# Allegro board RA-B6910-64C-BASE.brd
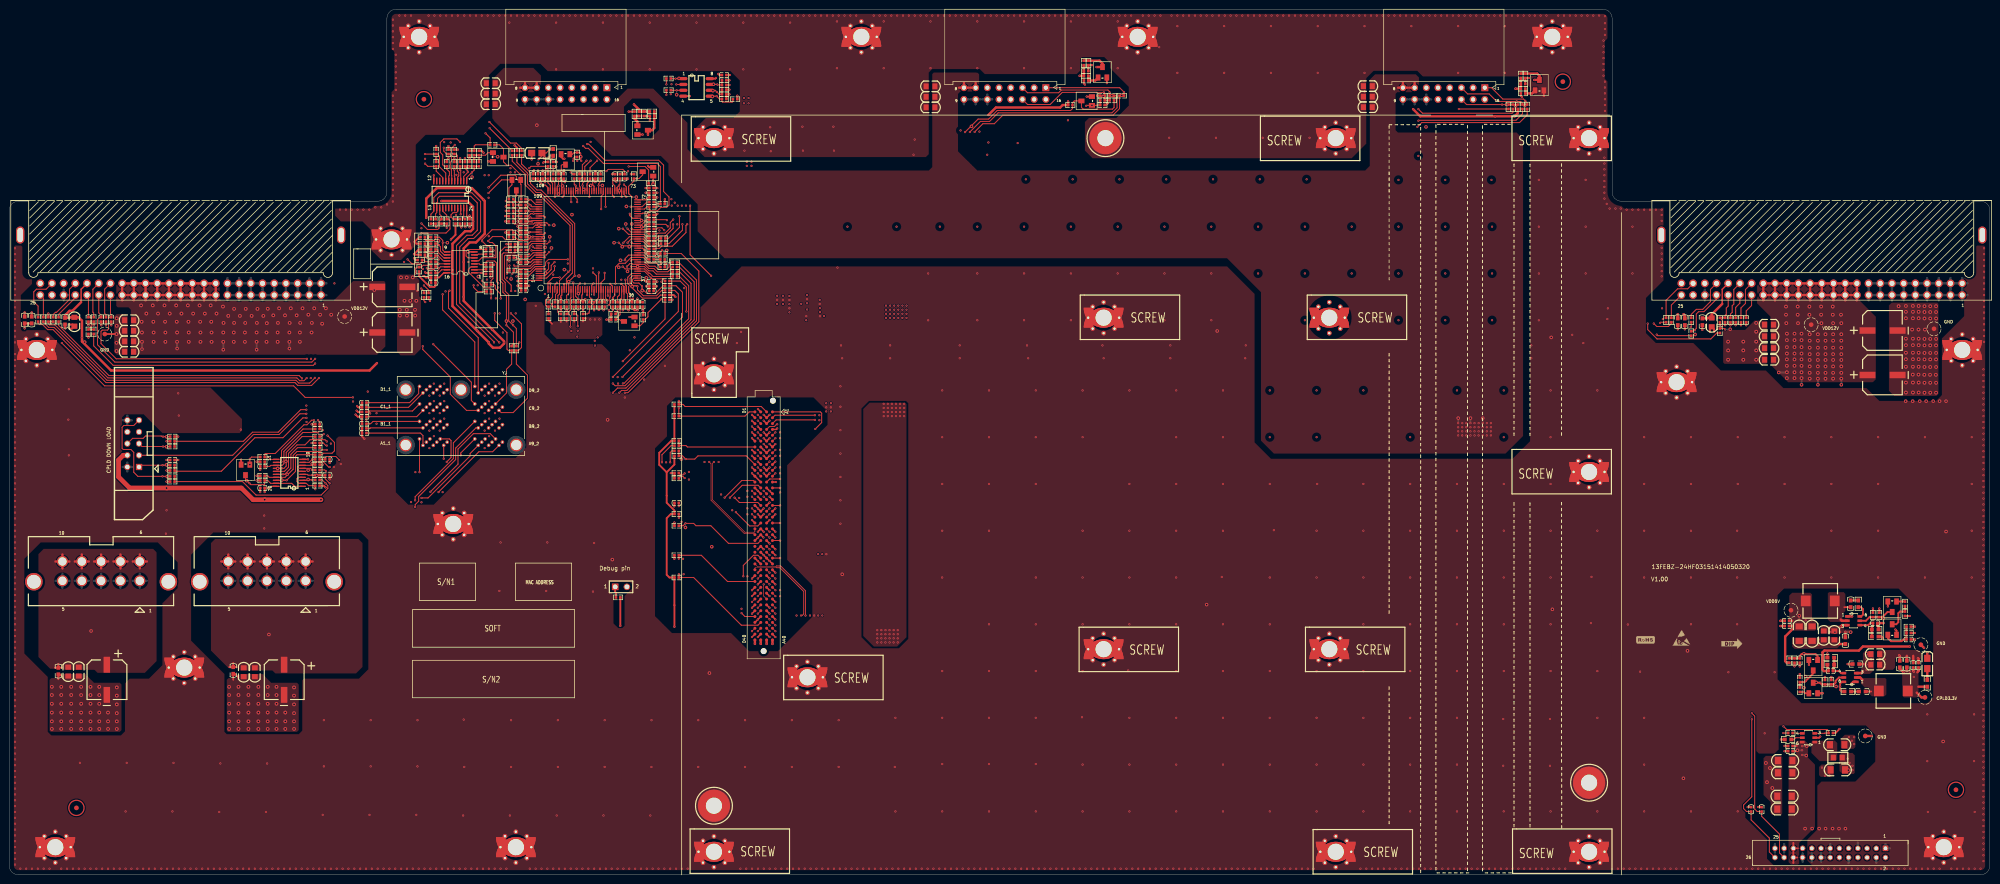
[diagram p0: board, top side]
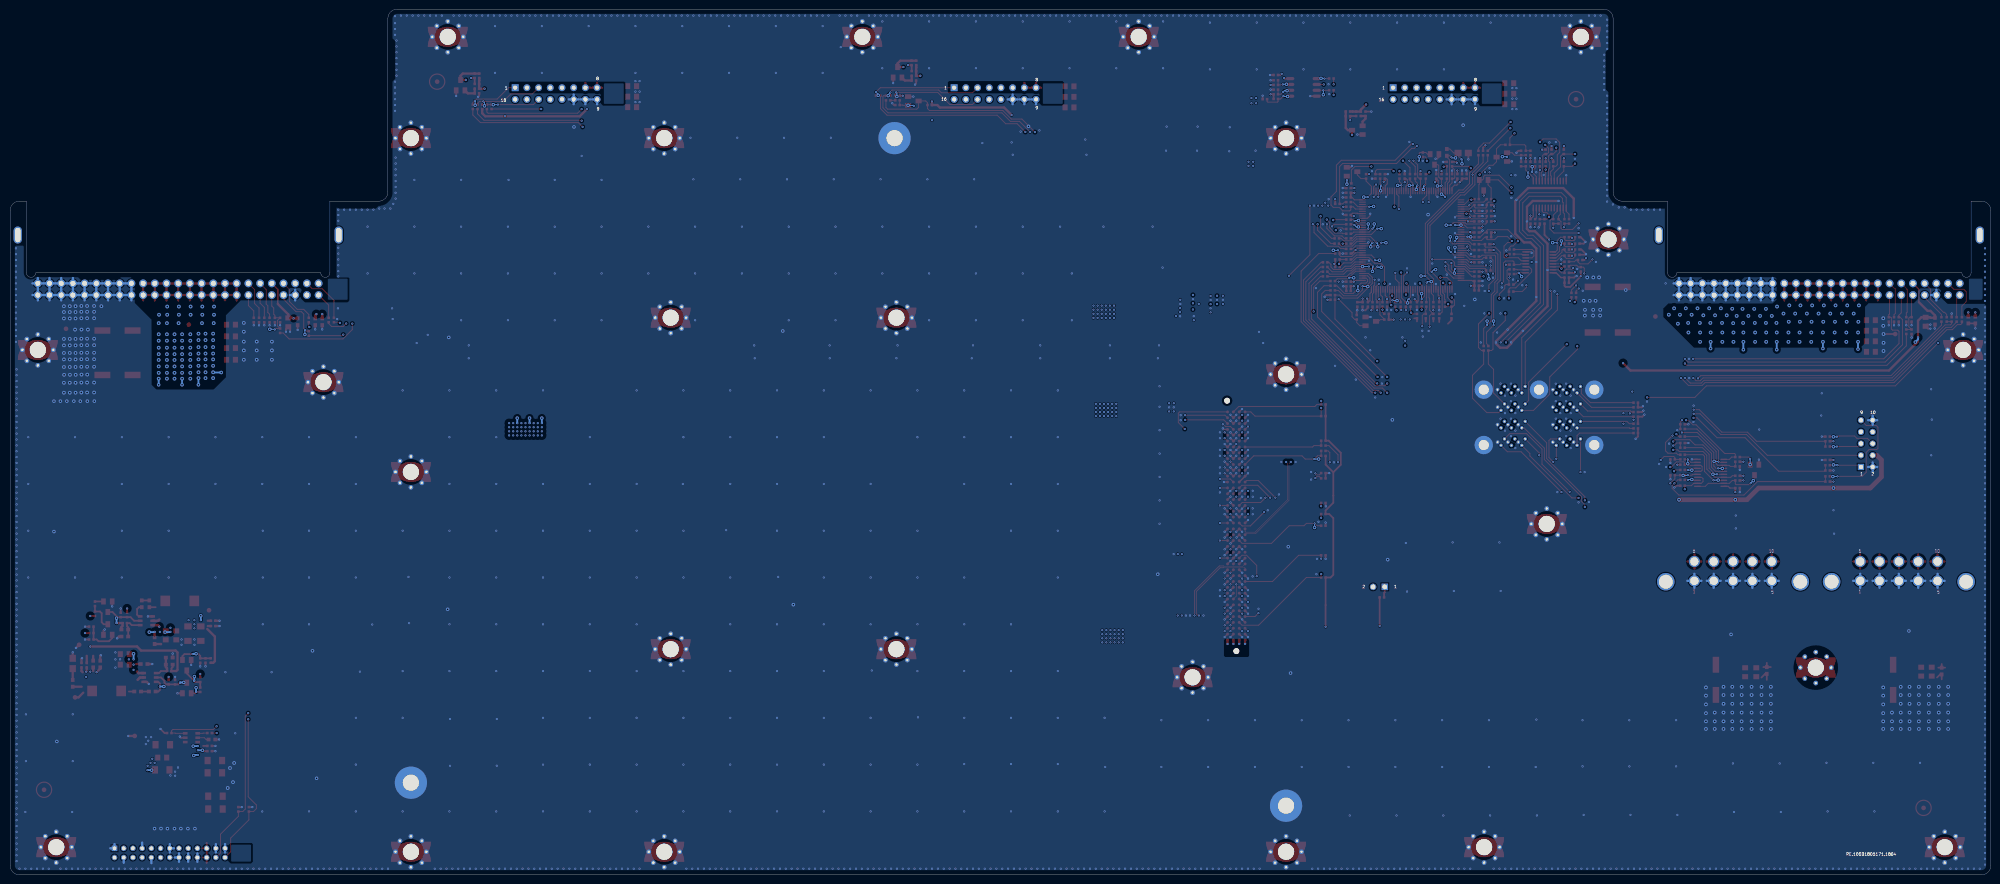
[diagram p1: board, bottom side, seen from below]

Outline 430 x 188 mm; copper layers: TOP, GND1, SIG1, GND2, SIG2, BOTTOM. Coordinates in mm from the lower left corner of the outline.
Outline path: 0,144.3 arc(0.12,144.98) 0.47,145.58 arc(1.15,146.11) 2,146.3 4.28,146.3 4.28,130.76 arc(4.39,130.31) 4.7,129.95 arc(5.46,129.78) 6.11,130.2 arc(6.24,130.47) 6.28,130.76 68.16,130.76 arc(68.21,130.46) 68.35,130.18 arc(69,129.78) 69.74,129.95 arc(70.05,130.31) 70.16,130.76 70.16,146.3 80,146.3 arc(81.41,146.89) 82,148.3 82,186 arc(82.59,187.41) 84,188 346,188 arc(347.41,187.41) 348,186 348,148.3 arc(348.59,146.89) 350,146.3 360.58,146.3 360.58,130.76 arc(360.69,130.31) 361,129.95 arc(361.76,129.78) 362.41,130.2 arc(362.54,130.47) 362.58,130.76 424.46,130.76 arc(424.51,130.46) 424.65,130.18 arc(425.3,129.78) 426.04,129.95 arc(426.35,130.31) 426.46,130.76 426.46,146.3 428,146.3 arc(429.41,145.71) 430,144.3 430,2 arc(429.41,0.59) 428,0 2,0 arc(0.59,0.59) 0,2 0,144.3

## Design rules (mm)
net group CIE_REFCLK_: nets PCIE_REFCLK_N PCIE_REFCLK_P
net group CU_CIE_RX0: nets CPU_PCIE_RXN0 CPU_PCIE_RXP0
net group CU_CIE_RX1: nets CPU_PCIE_RXN1 CPU_PCIE_RXP1
net group CU_CIE_RX2: nets CPU_PCIE_RXN2 CPU_PCIE_RXP2
net group CU_CIE_RX3: nets CPU_PCIE_RXN3 CPU_PCIE_RXP3
net group CU_CIE_TX0: nets CPU_PCIE_TXN0 CPU_PCIE_TXP0
net group CU_CIE_TX1: nets CPU_PCIE_TXN1 CPU_PCIE_TXP1
net group CU_CIE_TX2: nets CPU_PCIE_TXN2 CPU_PCIE_TXP2
net group CU_CIE_TX3: nets CPU_PCIE_TXN3 CPU_PCIE_TXP3
net group CU_KR_RD0: nets CPU_KR_RDN0 CPU_KR_RDP0
net group CU_KR_RD1: nets CPU_KR_RDN1 CPU_KR_RDP1
net group CU_KR_TD0: nets CPU_KR_TDN0 CPU_KR_TDP0
net group CU_KR_TD1: nets CPU_KR_TDN1 CPU_KR_TDP1
net group DP1: nets USB_DM USB_DP
net group MDI_0: nets MDI_0N MDI_0P
net group MDI_1: nets MDI_1N MDI_1P
net group MDI_2: nets MDI_2N MDI_2P
net group MDI_3: nets MDI_3N MDI_3P
net group USB_RX_: nets USB_RX_N USB_RX_P
net group USB_TX_: nets USB_TX_N USB_TX_P

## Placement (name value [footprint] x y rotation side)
C1  103  [C0402]  114.8 151.69 270 top
C2  0.1uF/25V  [C0402]  131.56 151.69 270 top
C3  0.1uF/25V  [C0402]  139.44 147.12 180 top
C4  0.1uF/25V  [C0402]  139.44 143.31 180 top
C5  103  [C0402]  136.39 123.88 90 top
C6  0.1uF/25V  [C0402]  111.62 128.96 0 top
C7  103  [C0402]  139.44 148.14 180 top
C8  0.1uF/25V  [C0402]  127.24 151.69 270 top
C9  0.1uF/25V  [C0402]  120.39 151.69 270 top
C10  0.1uF/25V  [C0402]  35.42 90.1 180 top
C16  1uF/25V  [C0402]  139.44 128.83 0 top
C17  1uF/25V  [C0402]  135.24 123.88 270 top
C18  10uF/6.3V  [C0402]  139.44 149.15 0 top
C19  10uF/6.3V  [C0402]  111.62 126.93 0 top
C20  10uF/6.3V  [C0402]  137.53 123.88 90 top
C21  0.1uF/25V  [C0402]  111.62 133.02 0 top
C22  103  [C0402]  111.62 127.94 0 top
C23  0.1uF/25V  [C0402]  139.44 134.93 180 top
C28  10uF/25V  [C0805]  200.01 166.68 0 top
C29  10uF/25V  [C0805]  200.01 168.96 180 top
C30  1uF/25V  [C0805]  200.01 171.25 180 top
C48  0.1uF/25V  [C0402]  124.58 123.88 90 top
C49  103  [C0402]  139.44 127.82 180 top
C50  103  [C0402]  131.05 123.88 90 top
C51  0.1uF/25V  [C0402]  119.75 123.88 90 top
C52  10uF/25V  [C0805]  104.55 171.93 0 top
C53  10uF/25V  [C0805]  104.55 169.64 180 top
C54  1uF/25V  [C0805]  104.55 167.36 180 top
C55  10uF/25V  [C0805]  294.97 171.3 0 top
C56  10uF/25V  [C0805]  294.97 169.01 180 top
C57  1uF/25V  [C0805]  294.97 166.72 180 top
C61  100P  [C0402]  111.62 144.2 180 top
C62  100P  [C0402]  111.62 145.47 180 top
C63  0.1uF/25V  [C0402]  54.98 84 0 top
C64  1uF/25V  [C0402]  111.62 139.5 180 top
C65  1uF/25V  [C0402]  111.62 141.91 180 top
C66  10uF/6.3V  [C0402]  113.78 151.69 90 top
C67  104  [C0603]  362.25 120.11 90 top
C68  104  [C0603]  363.78 120.11 90 top
C69  1uF/25V  [C0805]  382.07 111.86 0 top
C70  1uF/25V  [C0805]  382.07 114.4 0 top
C71  10uF/25V  [C0805]  382.07 116.94 0 top
C72  10uF/25V  [C0805]  382.07 119.48 0 top
C73  100P  [C0402]  374.83 120.5 90 top
C74  104  [C0603]  367.59 120.11 90 top
C75  100P  [C0402]  377.11 120.5 90 top
C77  10uF/25V  [C0805]  369.62 119.99 90 top
C78  100P  [C0402]  372.54 120.5 90 top
C79  104  [C0603]  3.35 120.5 90 top
C80  1uF/25V  [C0805]  26.02 115.88 0 top
C81  104  [C0603]  4.88 120.5 90 top
C82  1uF/25V  [C0805]  26.02 113.59 0 top
C83  10uF/25V  [C0805]  26.02 120.45 0 top
C84  10uF/25V  [C0805]  26.02 118.16 0 top
C85  100P  [C0402]  19.99 120.62 90 top
C86  100P  [C0402]  22.15 120.62 90 top
C87  104  [C0603]  12.12 120.24 90 top
C89  10uF/25V  [C0805]  14.15 120.11 90 top
C90  100P  [C0402]  17.2 120.62 90 top
C91  104  [C0603]  402.33 39.8 0 top
C92  X  [C0402]  395.47 44.25 0 top
C94  104  [C0603]  400.93 45.77 180 top
C95  10uF/25V  [C0805]  405.12 47.93 0 top
C96  10uF/25V  [C0805]  405.12 45.65 0 top
C97  22uF/6.3V  [C0603]  410.45 45.77 90 top
C98  22uF/6.3V  [C0603]  411.98 45.77 90 top
C99  1uF/25V  [C0402]  414.52 45.52 90 top
C100  0.1uF/25V  [C0402]  413.37 45.52 270 top
C101  X  [C0402]  412.38 51.11 180 top
C102  104  [C0603]  399.79 58.85 270 top
C103  X  [C0402]  405.12 54.66 180 top
C104  33uF/10V  [C1206]  396.99 22.79 180 top
C105  33uF/10V  [C1206]  396.86 28.25 0 top
C106  33uF/10V  [C1206]  385.56 24.82 180 top
C107  33uF/10V  [C1206]  385.56 22.15 180 top
C108  104  [C0603]  398.64 50.85 270 top
C109  10uF/25V  [C0805]  396.23 52 270 top
C110  10uF/25V  [C0805]  393.94 52 270 top
C111  33uF/10V  [C1206]  391.4 52.38 270 top
C112  33uF/10V  [C1206]  388.61 52.38 270 top
C113  1uF/25V  [C0402]  385.94 55.17 180 top
C114  0.1uF/25V  [C0402]  385.94 54.03 0 top
C116  0.1uF/25V  [C0402]  155.22 173.71 0 top
C117  0.1uF/25V  [C0402]  99.94 141.91 90 top
C120  33uF/10V  [C1206]  385.43 14.28 180 top
C121  33uF/10V  [C1206]  385.43 17.07 180 top
C129  X  [C0402]  380.46 14.22 90 top
C130  X  [C0402]  378.18 14.22 90 top
C131  104  [C0603]  10.66 44.25 90 top
C132  1uF/25V  [C0805]  12.82 44.12 90 top
C133  10uF/25V  [C0805]  15.1 44.12 90 top
C134  X  [C0402]  54.98 88.7 180 top
C135  X  [C0402]  69.08 86.79 0 top
C136  X  [C0402]  66.92 93.78 180 top
C137  X  [C0402]  66.92 97.84 180 top
C138  X  [C0402]  69.08 90.22 0 top
C139  X  [C0402]  133.59 151.69 270 top
C140  X  [C0402]  118.1 154.36 90 top
C141  X  [C0402]  142.86 125.91 0 top
C142  X  [C0402]  77.08 95.94 180 top
C143  X  [C0402]  77.08 96.95 180 top
C144  X  [C0402]  77.08 99.49 180 top
C145  X  [C0402]  77.08 97.97 180 top
C146  X  [C0402]  77.08 100.51 180 top
C147  X  [C0402]  77.08 102.54 180 top
C148  X  [C0402]  77.08 101.53 180 top
C149  X  [C0402]  144.9 80.77 180 top
C150  X  [C0402]  388.74 46.54 90 top
C151  104  [C0603]  48.63 44.38 90 top
C152  1uF/25V  [C0805]  53.33 44 90 top
C153  10uF/25V  [C0805]  50.92 44 90 top
C154  0.1uF/25V  [C0402]  92.06 129.72 0 top
C155  1uF/25V  [C0402]  92.06 128.58 0 top
C156  1uF/25V  [C0402]  115.81 151.69 270 top
C157  10uF/6.3V  [C0402]  139.44 126.8 180 top
C158  0.1uF/25V  [C0402]  386.7 26.85 0 top
CD1  220uF/25V  [CDNCC_0810]  406.7 118.21 180 top
CD2  220uF/25V  [CDNCC_0810]  406.7 108.56 180 top
CD4  220uF/25V  [CDNCC_0810]  83.17 117.78 180 top
CD5  220uF/25V  [CDNCC_0810]  83.17 127.69 180 top
CD7  220uF/25V  [CDNCC_0810]  21.2 42.34 90 top
CD8  220uF/25V  [CDNCC_0810]  59.68 42.34 90 top
D1  17_21_G6C_FM1N2B_3T  [LED_SMT0805]  114.54 156.77 0 top
D2  BAT54A  [SOT_23]  110.1 149.79 90 top
D3  17_21_G6C_FM1N2B_3T  [LED_SMT0805]  416.42 45.9 270 top
FD5  -  [MARK]  337.3 172.27 0 top
FD8  -  [MARK]  14.59 14.53 0 top
FD9  -  [MARK]  422.65 18.47 0 top
FD12  -  [MARK]  90.03 168.46 0 top
J1  -  [MOLEX_44068_0048]  64.35 63.85 0 top
J2  -  [C210R3-11631-Y]  320.36 170.95 180 top
J3  -  [MOLEX_44068_0048]  28.36 63.85 0 top
J4  -  [C210R3-11631-Y]  225.06 170.95 180 top
J5  -  [C210R3-11631-Y]  129.76 170.95 180 top
J7  -  [JP_10]  28.18 88.57 90 top
J8  -  [C210Q5_15033_Y]  424 125.91 180 top
J9  -  [C210Q5_15033_Y]  67.7 125.91 180 top
J10  -  [C200126087D6001P]  407.35 5.75 180 top
J11  -  [CON_2]  131.56 62.54 0 top
L1  3.3uH/3.8A  [L_7M50X7M50X4M70]  409.06 39.93 180 top
L2  3.3uH/3.8A  [L_7M50X7M50X4M70]  393.18 59.49 0 top
L3  300/2A  [L0805]  396.99 25.45 0 top
NOREF  -  []  95.08 93.97 90 top
NOREF#2  -  []  339.28 172.94 0 top
NOREF#3  -  []  87.45 113.52 90 top
NOREF#4  -  []  378.1 -31.45 90 top
NOREF#5  -  []  219.64 156.54 90 top
NOREF#6  -  []  105.4 48.44 0 top
NOREF#7  -  []  165.8 102.97 0 top
NOREF#8  -  []  167.37 54.07 0 top
NOREF#9  -  []  400.53 41.3 0 top
NOREF#10  -  []  402.38 114.91 0 top
NOREF#11  -  []  124.34 156.54 0 top
NOREF#12  -  []  124.34 172.94 0 top
NOREF#13  -  []  224.25 46.91 90 top
NOREF#14  -  []  55.42 38.07 0 top
NOREF#15  -  []  410.64 131.81 90 top
NOREF#16  -  []  67.7 128.45 90 top
NOREF#17  -  []  126.12 172.94 0 top
NOREF#18  -  []  425.02 143.48 180 top
NOREF#19  -  []  161.9 100.54 0 top
NOREF#20  -  []  389.77 28.22 0 top
NOREF#21  -  []  221.42 172.94 0 top
NOREF#22  -  []  161.9 51.01 90 top
NOREF#23  -  []  207.28 168.41 0 top
NOREF#24  -  []  4.88 143.56 0 top
NOREF#25  -  []  93.58 94.67 0 top
NOREF#26  -  []  314.94 156.54 90 top
NOREF#27  -  []  207.28 168.41 90 top
NOREF#28  -  []  363.04 125.91 0 top
NOREF#29  -  []  2.38 138.95 0 top
NOREF#30  -  []  81 174.68 180 top
NOREF#31  -  []  78.85 124.39 0 top
NOREF#32  -  []  412.81 40.63 0 top
NOREF#33  -  []  316.72 172.94 0 top
NOREF#34  -  []  166.97 105.11 0 top
NOREF#35  -  []  243.98 172.94 0 top
NOREF#36  -  []  207.28 170.95 0 top
NOREF#37  -  []  389.43 55.74 90 top
NOREF#38  -  []  16.93 38.07 0 top
NOREF#39  -  []  -69.52 146.43 0 top
NOREF#40  -  []  349 176.96 0 top
NOREF#41  -  []  282.9 146.43 0 top
NOREF#42  -  []  74.63 147.3 90 top
NOREF#43  -  []  399.07 56.12 0 top
NOREF#44  -  []  74.09 103.19 90 top
NOREF#45  -  []  310.2 168.41 0 top
NOREF#46  -  []  314.94 156.54 0 top
NOREF#47  -  []  358.68 138.95 0 top
NOREF#48  -  []  425 183 270 top
NOREF#49  -  []  14.98 131.81 90 top
NOREF#50  -  []  163.79 48.58 90 top
NOREF#51  -  []  84.25 108.24 0 top
NOREF#52  -  []  402.38 105.26 0 top
NOREF#53  -  []  403.43 118.21 0 top
NOREF#54  -  []  95.08 135.3 0 top
NOREF#55  -  []  111.98 168.41 0 top
NOREF#56  -  []  99.82 130.48 90 top
NOREF#57  -  []  2.38 138.95 0 top
NOREF#58  -  []  410.98 113.95 90 top
NOREF#59  -  []  78.85 114.48 0 top
NOREF#60  -  []  214.9 168.41 0 top
NOREF#61  -  []  65.16 125.91 0 top
NOREF#62  -  []  107.08 93.97 90 top
NOREF#63  -  []  430.39 103.19 90 top
NOREF#64  -  []  79.9 127.69 0 top
NOREF#65  -  []  165.8 102.97 0 top
NOREF#66  -  []  167.37 46.91 0 top
NOREF#67  -  []  16.93 38.07 0 top
NOREF#68  -  []  399.55 56.72 0 top
NOREF#69  -  []  55.42 38.07 0 top
NOREF#70  -  []  101.84 130.36 90 top
NOREF#71  -  []  389.43 63.24 0 top
NOREF#72  -  []  148.68 172.94 0 top
NOREF#73  -  []  424 125.91 90 top
NOREF#74  -  []  398.31 41.9 0 top
NOREF#75  -  []  340.06 156.54 90 top
NOREF#76  -  []  302.58 168.41 90 top
NOREF#77  -  []  354.7 147.3 90 top
NOREF#78  -  []  92.83 93.97 0 top
NOREF#79  -  []  358.68 138.95 0 top
NOREF#80  -  []  421.46 125.91 0 top
NOREF#81  -  []  167.37 46.91 90 top
NOREF#82  -  []  67.7 125.91 90 top
NOREF#83  -  []  21.2 39.07 90 top
NOREF#84  -  []  389.77 28.22 90 top
NOREF#85  -  []  424 128.45 90 top
NOREF#86  -  []  164.44 51.01 0 top
NOREF#87  -  []  161.9 57.36 90 top
NOREF#88  -  []  95.08 134.65 90 top
NOREF#89  -  []  383.35 3.75 0 top
NOREF#90  -  []  6.74 128.45 90 top
NOREF#91  -  []  244.76 156.54 90 top
NOREF#92  -  []  410.98 104.29 90 top
NOREF#93  -  []  124.34 156.54 90 top
NOREF#94  -  []  166.97 108.82 90 top
NOREF#95  -  []  363.08 50.35 0 top
NOREF#96  -  []  94.33 93.27 90 top
NOREF#97  -  []  111.98 168.41 90 top
NOREF#98  -  []  111.98 170.95 0 top
NOREF#99  -  []  89.08 106.07 90 top
NOREF#100  -  []  87.45 123.42 90 top
NOREF#101  -  []  402.28 41.3 90 top
NOREF#102  -  []  161.9 51.01 0 top
NOREF#103  -  []  6.74 125.91 0 top
NOREF#104  -  []  397.81 39.23 90 top
NOREF#105  -  []  167.37 46.91 90 top
NOREF#106  -  []  72.06 138.95 90 top
NOREF#107  -  []  -62.73 168.05 0 top
NOREF#108  -  []  79.9 117.78 0 top
NOREF#109  -  []  403.43 108.56 0 top
NOREF#110  -  []  58.16 131.81 90 top
NOREF#111  -  []  428.36 138.95 90 top
NOREF#112  -  []  302.58 168.41 0 top
NOREF#113  -  []  59.68 39.07 90 top
NOREF#114  -  []  163.79 48.58 90 top
NOREF#115  -  []  401.3 53.62 90 top
NOREF#116  -  []  119.6 168.41 0 top
NOREF#117  -  []  401.77 55.17 90 top
NOREF#118  -  []  168.32 105.11 90 top
NOREF#119  -  []  389.29 28.82 0 top
NOREF#120  -  []  405.91 39.93 0 top
NOREF#121  -  []  96.13 130.47 90 top
NOREF#122  -  []  84.25 91.04 90 top
NOREF#123  -  []  -3.54 146.43 0 top
NOREF#124  -  []  219.64 156.54 0 top
NOREF#125  -  []  373.37 50.98 0 top
NOREF#126  -  []  372.54 131.81 90 top
NOREF#127  -  []  219.64 172.94 0 top
NOREF#128  -  []  95.08 105.37 90 top
NOREF#129  -  []  354.95 50.98 0 top
NOREF#130  -  []  314.94 172.94 0 top
NOREF#131  -  []  398.31 41.9 90 top
NOREF#132  -  []  107.08 93.97 90 top
NOREF#133  -  []  107.08 93.97 90 top
NOREF#134  -  []  89.08 106.07 0 top
NOREF#135  -  []  390.03 59.49 0 top
NOREF#136  -  []  286.78 146.43 0 top
NOREF#137  -  []  149.46 156.54 90 top
NOREF#138  -  []  352.76 146.43 0 top
NOREF#139  -  []  -73.4 146.43 0 top
NOREF#140  -  []  363.04 128.45 90 top
NOREF#141  -  []  293.57 168.05 0 top
NOREF#142  -  []  224.25 46.91 90 top
NOREF#143  -  []  302.58 170.95 0 top
NOREF#144  -  []  5 183 270 bottom
Q1  MMBT3904LT1G  [SOT_23]  120.77 155.37 90 top
Q3  MMBT3904LT1G  [SOT_23]  138.67 152.71 0 top
Q4  MMBT3904LT1G  [SOT_23]  51.3 87.94 90 top
Q7  MMBT3904LT1G  [SOT_23]  408.8 58.22 90 top
Q8  MMBT3904LT1G  [SOT_23]  408.8 53.27 270 top
Q9  MMBT3904LT1G  [SOT_23]  391.66 40.57 270 top
Q10  MMBT3904LT1G  [SOT_23]  391.66 45.52 90 top
Q11  MMBT3904LT1G  [SOT_23]  134.61 120.2 0 top
Q12  MMBT3904LT1G  [SOT_23]  233.92 168.07 0 top
Q13  MMBT3904LT1G  [SOT_23]  106.16 155.88 180 top
Q14  MMBT3904LT1G  [SOT_23]  332.22 171.5 270 top
Q15  MMBT3904LT1G  [SOT_23]  237.35 174.3 270 top
Q16  MMBT3904LT1G  [SOT_23]  137.53 161.72 180 top
R1  X  [R0402]  18.34 117.96 90 top
R2  X  [R0402]  371.4 118.16 90 top
R4  33  [R0402]  109.08 131.24 180 top
R6  33  [R0402]  123.56 123.88 270 top
R16  33  [R0402]  111.62 138.48 180 top
R17  4.7K  [R0402]  111.62 140.52 180 top
R20  33  [R0402]  118.1 151.69 90 top
R31  33  [R0402]  118.48 123.88 270 top
R45  4.7K  [R0402]  35.42 87.81 180 top
R46  4.7K  [R0402]  35.42 94.16 180 top
R47  4.7K  [R0402]  35.42 85.4 180 top
R48  100_1%  [R0402]  35.42 88.95 180 top
R49  100_1%  [R0402]  35.42 93.02 180 top
R51  100_1%  [R0402]  35.42 86.54 180 top
R54  33  [R0402]  129.28 123.88 270 top
R58  33  [R0402]  111.62 129.97 180 top
R69  X  [R0402]  144.9 87.24 180 top
R75  X  [R0402]  144.9 93.21 0 top
R81  X  [R0402]  144.9 92.07 0 top
R87  X  [R0402]  144.9 86.1 180 top
R89  4.7K  [R0402]  108.96 141.91 180 top
R96  33  [R0402]  329.55 166.8 90 top
R97  33  [R0402]  328.54 166.8 90 top
R98  1K  [R0402]  326.51 166.8 270 top
R99  33  [R0402]  241.54 169.22 0 top
R100  33  [R0402]  239.38 169.22 180 top
R101  1K  [R0402]  237.35 168.2 180 top
R102  33  [R0402]  109.21 156.77 90 top
R103  33  [R0402]  111.24 156.77 90 top
R104  1K  [R0402]  100.95 156.77 270 top
R109  10K_1%  [R0402]  116.96 151.69 90 top
R110  X  [R0402]  116.96 154.36 90 top
R112  4.7K  [R0402]  142.86 124.89 0 top
R113  4.7K  [R0402]  119.24 151.69 90 top
R115  X  [R0402]  108.96 138.48 180 top
R116  33  [R0402]  111.62 134.29 180 top
R117  4.7K  [R0402]  123.31 156.39 270 top
R118  4.7K  [R0402]  111.62 130.99 180 top
R119  475_1%  [R0603]  118.1 156.9 90 top
R121  33  [R0402]  109.08 134.04 180 top
R122  4.7K  [R0402]  123.81 151.69 90 top
R123  X  [R0402]  108.96 139.5 180 top
R124  33  [R0402]  124.96 151.69 90 top
R125  33  [R0402]  126.1 151.69 90 top
R126  33  [R0402]  139.44 135.94 0 top
R127  10K_1%  [R0402]  108.96 143.06 180 top
R128  33  [R0402]  128.39 151.69 90 top
R129  33  [R0402]  141.98 137.09 0 top
R130  10K_1%  [R0402]  111.62 143.06 180 top
R131  4.7K  [R0402]  108.96 144.2 0 top
R132  33  [R0402]  139.44 138.23 0 top
R133  4.7K  [R0402]  108.96 145.47 0 top
R134  33  [R0402]  139.44 139.25 0 top
R135  10K_1%  [R0402]  108.96 146.74 180 top
R136  33  [R0402]  139.44 140.26 0 top
R137  33  [R0402]  139.44 141.28 0 top
R138  10K_1%  [R0402]  111.62 146.74 180 top
R139  33  [R0402]  139.44 142.29 0 top
R140  33  [R0402]  132.58 151.69 90 top
R143  4.7K  [R0402]  135.63 151.69 90 top
R145  4.7K  [R0402]  139.31 150.17 180 top
R146  33  [R0402]  66.92 91.24 0 top
R147  33  [R0402]  66.92 92.76 0 top
R148  33  [R0402]  66.92 95.18 0 top
R149  33  [R0402]  66.92 96.83 0 top
R150  10K_1%  [R0402]  54.98 85.65 0 top
R151  33  [R0402]  66.92 85.78 0 top
R152  33  [R0402]  66.92 86.79 0 top
R153  10K_1%  [R0402]  54.98 90.73 180 top
R154  X  [R0402]  121.02 121.34 270 top
R155  33  [R0402]  66.92 87.94 0 top
R156  33  [R0402]  66.92 90.22 0 top
R157  33  [R0402]  122.54 123.88 270 top
R158  X  [R0402]  122.67 121.34 270 top
R160  4.7K  [R0402]  134.23 123.88 270 top
R161  4.7K  [R0402]  133.21 123.88 270 top
R163  4.7K  [R0402]  128.13 123.88 270 top
R164  4.7K  [R0402]  126.99 123.88 270 top
R166  4.7K  [R0402]  119.75 121.34 270 top
R167  4.7K  [R0402]  121.02 123.88 270 top
R171  4.7K  [R0402]  35.42 95.18 0 top
R172  33  [R0402]  375.97 120.5 270 top
R173  33  [R0402]  373.68 120.5 270 top
R174  200  [R0402]  371.4 120.5 90 top
R175  33  [R0402]  365.18 117.57 90 top
R176  X  [R0402]  365.18 120.5 270 top
R177  33  [R0402]  359.71 120.5 270 top
R178  33  [R0402]  360.86 120.5 90 top
R180  0  [R0402]  8.5 120.62 90 top
R181  X  [R0402]  21.01 120.62 270 top
R182  X  [R0402]  18.34 120.62 270 top
R183  200  [R0402]  17.2 117.96 90 top
R184  33  [R0402]  10.72 120.62 90 top
R185  X  [R0402]  9.58 120.62 270 top
R186  33  [R0402]  6.27 120.62 270 top
R187  33  [R0402]  7.42 120.62 90 top
R192  0  [R0603]  399.15 39.8 0 top
R193  10K_1%  [R0402]  404.61 56.44 270 top
R194  475_1%  [R0603]  416.42 41.58 90 top
R195  33K_1%  [R0603]  395.47 45.65 0 top
R196  10K_1%  [R0402]  411.6 56.7 90 top
R197  2.2K  [R0402]  411.6 58.85 90 top
R198  2.2K  [R0402]  406.01 56.44 90 top
R199  10K_1%  [R0402]  412.38 52.5 180 top
R200  1K  [R0402]  412.38 53.9 180 top
R201  10K_1%  [R0603]  395.47 47.17 0 top
R202  0  [R0603]  401.44 58.85 90 top
R204  60.4K_1%  [R0603]  405.12 53.27 180 top
R205  10K_1%  [R0402]  386.7 27.99 180 top
R206  33K_1%  [R0603]  386.2 29.39 180 top
R207  11K_1%  [R0603]  405.12 51.74 0 top
R208  33  [R0402]  386.7 30.79 180 top
R209  10K_1%  [R0402]  395.47 30.79 180 top
R219  33  [R0402]  143.15 172.95 0 top
R220  4.7K  [R0402]  155.22 171.55 0 top
R221  33  [R0402]  143.15 170.41 0 top
R222  X  [R0402]  155.22 172.57 0 top
R223  4.7K  [R0402]  155.22 170.53 0 top
R224  X  [R0402]  155.22 169.52 0 top
R225  X  [R0402]  155.22 168.5 0 top
R226  4.7K  [R0402]  157.6 168.46 0 top
R227  10K_1%  [R0402]  96.64 157.03 270 top
R228  10K_1%  [R0402]  96.64 154.36 270 top
R229  10K_1%  [R0402]  95.37 157.03 270 top
R230  10K_1%  [R0402]  94.99 154.36 270 top
R231  10K_1%  [R0402]  92.7 157.03 270 top
R232  10K_1%  [R0402]  92.7 154.36 270 top
R235  4.7K  [R0402]  91.56 141.91 90 top
R236  4.7K  [R0402]  92.57 141.91 90 top
R237  4.7K  [R0402]  93.84 141.91 90 top
R238  4.7K  [R0402]  94.99 141.91 90 top
R239  33  [R0402]  98.92 141.91 90 top
R240  4.7K  [R0402]  97.91 154.36 270 top
R241  X  [R0402]  100.95 154.36 270 top
R242  X  [R0402]  99.94 154.36 270 top
R243  X  [R0402]  96.89 141.91 90 top
R244  4.7K  [R0402]  101.97 154.36 270 top
R245  4.7K  [R0402]  98.92 154.36 270 top
R246  4.7K  [R0402]  97.91 141.91 90 top
R247  0  [R0402]  110.1 114.35 90 top
R248  0  [R0402]  109.08 114.35 90 top
R249  0  [R0402]  142.86 128.96 0 top
R250  0  [R0402]  139.44 137.09 0 top
R251  0  [R0402]  141.98 138.23 0 top
R252  X  [R0402]  66.92 89.08 180 top
R253  X  [R0402]  66.92 84.51 180 top
R254  X  [R0402]  54.98 86.67 0 top
R255  4.7K  [R0402]  54.98 89.72 0 top
R256  X  [R0402]  144.9 94.29 180 top
R257  X  [R0402]  144.9 90.99 180 top
R258  X  [R0402]  144.9 78.35 0 top
R259  X  [R0402]  144.9 75.81 0 top
R260  X  [R0402]  144.9 64.57 0 top
R261  10K_1%  [R0402]  395.59 41.84 270 top
R262  10K_1%  [R0402]  388.74 42.34 270 top
R263  2.2K  [R0402]  388.74 40.19 270 top
R264  2.2K  [R0402]  394.2 41.84 90 top
R265  10K_1%  [R0402]  386.45 46.54 90 top
R266  2.2K  [R0402]  387.59 46.54 90 top
R267  33  [R0402]  122.67 151.69 90 top
R268  X  [R0402]  141.85 132.01 0 top
R269  33  [R0402]  139.44 133.66 0 top
R270  X  [R0402]  141.85 133.66 0 top
R271  X  [R0402]  139.44 145.09 0 top
R272  33  [R0402]  139.44 146.1 0 top
R273  X  [R0402]  141.85 145.72 0 top
R274  X  [R0402]  144.9 102.16 180 top
R275  X  [R0402]  144.9 99.62 180 top
R276  X  [R0402]  144.9 69.4 180 top
R277  4.7K  [R0402]  131.18 120.58 0 top
R278  1K  [R0402]  327.52 166.8 270 top
R279  1K  [R0402]  137.66 121.08 270 top
R280  4.7K  [R0402]  230.37 167.19 0 top
R281  1K  [R0402]  237.35 169.22 180 top
R282  1K  [R0402]  237.35 167.19 180 top
R283  4.7K  [R0402]  110.23 156.77 270 top
R284  1K  [R0402]  99.94 156.77 270 top
R285  1K  [R0402]  101.97 156.77 270 top
R289  4.7K  [R0402]  89.78 138.48 180 top
R290  33  [R0402]  104 130.48 180 top
R291  33  [R0402]  104 131.5 180 top
R292  X  [R0402]  92.06 138.48 180 top
R293  100K_1%  [R0402]  89.78 137.09 180 top
R294  X  [R0402]  92.06 137.09 180 top
R295  4.7K  [R0402]  89.78 135.82 180 top
R296  X  [R0402]  92.06 135.82 180 top
R297  4.7K  [R0402]  104 132.51 180 top
R298  4.7K  [R0402]  89.78 134.67 180 top
R299  X  [R0402]  92.06 134.47 180 top
R300  33  [R0402]  92.06 133.15 180 top
R301  33  [R0402]  104 135.82 180 top
R302  33  [R0402]  92.06 132.13 180 top
R303  33  [R0402]  104 134.8 180 top
R304  1K  [R0402]  89.02 131.5 90 top
R305  4.7K  [R0402]  92.06 130.74 180 top
R306  1K  [R0402]  89.14 133.53 0 top
R307  X  [R0402]  104.13 126.67 0 top
R308  X  [R0402]  104.13 128.2 0 top
R309  X  [R0402]  90.03 125.91 90 top
R310  X  [R0402]  91.05 125.91 90 top
R311  X  [R0402]  325.49 166.8 270 top
R312  X  [R0402]  239.38 168.2 0 top
R313  X  [R0402]  104.89 158.55 0 top
R314  X  [R0402]  142.86 127.94 0 top
R315  X  [R0402]  142.86 126.93 0 top
R316  X  [R0402]  144.52 129.97 0 top
R317  X  [R0402]  144.52 130.99 0 top
R318  4.7K  [R0402]  109.34 135.69 180 top
R319  4.7K  [R0402]  109.34 136.96 180 top
R320  X  [R0402]  144.52 132.01 0 top
R321  33  [R0402]  111.62 135.69 180 top
R322  X  [R0402]  144.52 133.02 0 top
R323  33  [R0402]  111.62 136.96 180 top
R324  X  [R0402]  141.85 134.93 0 top
R325  33  [R0402]  117.08 123.88 270 top
R326  33  [R0402]  125.97 123.88 270 top
R327  33  [R0402]  132.07 123.88 270 top
R328  X  [R0402]  329.17 173.54 90 top
R329  X  [R0402]  328.67 171.76 0 top
R330  X  [R0402]  328.16 173.54 90 top
R331  X  [R0402]  328.67 170.74 0 top
R332  X  [R0402]  328.67 169.73 0 top
R333  4.7K  [R0402]  131.18 121.85 180 top
R339  4.7K  [R0402]  124.58 121.34 270 top
R345  4.7K  [R0402]  117.08 121.34 270 top
R346  X  [R0402]  234.3 176.33 90 top
R347  X  [R0402]  233.8 174.55 0 top
R348  X  [R0402]  233.29 176.33 90 top
R349  X  [R0402]  233.8 173.54 0 top
R350  X  [R0402]  233.8 172.52 0 top
R351  X  [R0402]  139.56 164.77 0 top
R352  X  [R0402]  137.78 165.28 270 top
R353  X  [R0402]  139.56 165.79 0 top
R354  X  [R0402]  136.77 165.28 270 top
R355  X  [R0402]  135.75 165.28 270 top
R356  4.7K  [R0402]  132.2 60.25 0 top
U1  LCMXO2_1200HC_4TG144C  [TQFP_144_1M60]  125.72 137.85 90 top
U2  SN74LVC244APWRG4  [TSSOP_20]  60.82 87.3 90 top
U3  TPS563201  [SOT23_6_1M10]  399.66 42.85 180 top
U4  TPS563201  [SOT23_6_1M10]  400.42 55.17 0 top
U5  TPS2553DDBVR  [SOT23_6_1M45]  390.64 29.77 180 top
U7  LM75AIM  [SO_8]  149.22 171.02 270 top
U8  PCA9548APW  [TSSOP_24]  95.75 147.75 180 top
U9  -  [46557-4145]  163.79 48.58 90 top
U10  PCA9641PW  [TSSOP_16_1M10]  98.03 133.02 90 top
X18  -  [TEST_40]  391.21 119.48 0 top
X19  -  [TEST_40]  417.88 118.59 0 top
X20  -  [TEST_40]  72.82 121.26 0 top
X21  -  [TEST_40]  20.75 117.45 0 top
X22  -  [TEST_40]  415.91 38.53 180 top
X23  -  [TEST_40]  415.03 49.96 180 top
X24  -  [TEST_40]  386.83 57.46 0 top
X25  -  [TEST_40]  402.96 30.15 180 top
X26  -  [SCREW_N_M_3_5MM]  10 6 0 top
X27  -  [SCREW_N_M_3_5MM]  153 5 0 top
X28  -  [SCREW_N_M_3_5MM]  6 114 0 top
X29  -  [SCREW_N_M_3_5MM]  96.4 76.2 0 top
X30  -  [SCREW_N_M_3_5MM]  83 138 0 top
X31  -  [SCREW_N_M_3_5MM]  153 108.7 0 top
X32  -  [SCREW_N_M_3_5MM]  173.3 42.9 0 top
X33  -  [SCREW_N_M_3_5MM]  89 182 0 top
X34  -  [SCREW_N_M_3_5MM]  153 160 0 top
X35  -  [SCREW_N_M_3_5MM]  237.6 49 0 top
X36  -  [SCREW_N_M_3_5MM]  237.6 121 0 top
X37  -  [SCREW_N_M_3_5MM]  288 5 0 top
X38  -  [SCREW_N_M_3_5MM]  286.6 49 0 top
X39  -  [SCREW_N_M_3_5MM]  185 182 0 top
X40  -  [SCREW_N_M_3_5MM]  245 182 0 top
X41  -  [SCREW_N_M_3_5MM]  343 5 0 top
X42  -  [SCREW_N_M_3_5MM]  288 160 0 top
X43  -  [SCREW_N_M_3_5MM]  286.6 121 0 top
X44  -  [SCREW_N_M_3_5MM]  343 87.5 0 top
X45  -  [SCREW_N_M_3_5MM]  335 182 0 top
X46  -  [SCREW_N_M_3_5MM]  420 6 0 top
X47  -  [SCREW_HOLE_3_5MM]  238 160 0 top
X48  -  [SCREW_N_M_3_5MM]  424 114 0 top
X49  -  [SCREW_N_M_3_5MM]  362 107 0 top
X50  -  [SCREW_N_M_3_5MM]  343 160 0 top
X54  -  [SCREW_N_M_3_5MM]  38 45 0 top
X55  -  [SCREW_HOLE_3_5MM]  343 20 0 top
X56  -  [SCREW_HOLE_3_5MM]  153 15 0 top
X58  -  [SCREW_N_M_3_5MM]  110 6 0 top
YJ1  -  [10120667-101LF]  110.08 93.34 90 top

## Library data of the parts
C1-C10 C16 C17 C21-C23 C48-C51 C61-C65 C73 C75 C78 C85 C86 C90 C92 C99-C101 C103 C113 C114 C116 C117 C129 C130 C134-C150 C154-C156 C158 = C0402: alternate symbols: (c0402;c0402_p;c0402_ap)
C18-C20 C66 C157 = C0402_P: alternate symbols: (c0402;c0402_p)
C28-C30 C52-C57 C69-C72 C77 C80 C82-C84 C89 C95 C96 C109 C110 C132 C133 C152 C153 = C0805: alternate symbols: (C0805;C0805_ap)
C67 C68 C74 C79 C81 C87 C91 C94 C97 C98 C102 C108 C131 C151 = C0603: alternate symbols: (C0603;C0603_ap)
C104-C107 C111 C112 C120 C121 = C1206: alternate symbols: (C1206;C1206_ap)
CD1 CD2 CD4 CD5 CD7 CD8 = CDNCC_0810_AP: alternate symbols: (CDNCC_0810;CDNCC_0810_AP)
D1 D3 = LED_2P
D2 = BAT54A_AP: alternate symbols: (SOT_23;SOT_23_AP)
FD5 FD8 FD9 FD12 = MARK
J1 J3 = MOLEX_44068_0048
J2 J4 J5 = C210R3-11631-Y
J7 = JP_10
J8 J9 = C210Q5_15033_Y
J10 = CON_2X13_N
J11 = CON_2
L1 L2 = Inductor
L3 = L0805: alternate symbols: (L0805;L0805_AP)
Q1 Q3 Q4 Q7-Q16 = BCE_NPN_AP: alternate symbols: (SOT_23;SOT_23_AP)
R1 R2 R4 R6 R16 R17 R20 R31 R45-R49 R51 R54 R58 R69 R75 R81 R87 R89 R96-R104 R109 R110 R112 R113 R115-R118 R121-R140 R143 R145-R158 R160 R161 R163 R164 R166 R167 R171-R178 R180-R187 R193 R196-R200 R205 R208 R209 R219-R232 R235-R285 R289-R333 R339 R345-R356 = R0402: alternate symbols: (r0402,r0402_p,R0402_AP)
R119 R192 R194 R195 R201 R202 R204 R206 R207 = R0603: alternate symbols: (R0603,R0603_AP)
U1 = LCMXO2_1200HC_4TG144C
U2 = 74LVC244A
U3 U4 = TPS563201
U5 = TPS2553DDBVR
U7 = LM75A
U8 = PCA9548APW
U9 = 46557-4145
U10 = PCA9641PW
X18-X25 = TEST_40: alternate symbols: (TEST_40;TEST_40_1)
X26-X46 X48-X50 X54 X58 = SCREW_N
X47 X55 X56 = SCREW_HOLE_3_5MM
YJ1 = 10120667-101LF: tolerance: V10C

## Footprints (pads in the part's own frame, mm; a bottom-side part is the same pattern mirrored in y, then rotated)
46557-4145
  round 1.27 hole 1.27 unplated: (0,0) (54.39,-2.01)
  round 0.635 smd: A1(51.96,-1.91) A2(50.69,-1.91) A3(49.42,-1.91) A4(48.15,-1.91) A5(46.88,-1.91) A6(45.61,-1.91) A7(44.34,-1.91) A8(43.07,-1.91) A9(41.8,-1.91) A10(40.53,-1.91) A11(39.26,-1.91) A12(37.99,-1.91) A13(36.72,-1.91) A14(35.45,-1.91) A15(34.18,-1.91) A16(32.91,-1.91) A17(31.64,-1.91) A18(30.37,-1.91) A19(29.1,-1.91) A20(27.83,-1.91) A21(26.56,-1.91) A22(25.29,-1.91) A23(24.02,-1.91) A24(22.75,-1.91) A25(21.48,-1.91) A26(20.21,-1.91) A27(18.94,-1.91) A28(17.67,-1.91) A29(16.4,-1.91) A30(15.13,-1.91) A31(13.86,-1.91) A32(12.59,-1.91) A33(11.32,-1.91) A34(10.05,-1.91) A35(8.78,-1.91) A36(7.51,-1.91) A37(6.24,-1.91) A38(4.97,-1.91) A39(3.7,-1.91) A40(2.43,-1.91) B1(51.96,-0.64) B2(50.69,-0.64) B3(49.42,-0.64) B4(48.15,-0.64) B5(46.88,-0.64) B6(45.61,-0.64) B7(44.34,-0.64) B8(43.07,-0.64) B9(41.8,-0.64) B10(40.53,-0.64) B11(39.26,-0.64) B12(37.99,-0.64) B13(36.72,-0.64) B14(35.45,-0.64) B15(34.18,-0.64) B16(32.91,-0.64) B17(31.64,-0.64) B18(30.37,-0.64) B19(29.1,-0.64) B20(27.83,-0.64) B21(26.56,-0.64) B22(25.29,-0.64) B23(24.02,-0.64) B24(22.75,-0.64) B25(21.48,-0.64) B26(20.21,-0.64) B27(18.94,-0.64) B28(17.67,-0.64) B29(16.4,-0.64) B30(15.13,-0.64) B31(13.86,-0.64) B32(12.59,-0.64) B33(11.32,-0.64) B34(10.05,-0.64) B35(8.78,-0.64) B36(7.51,-0.64) B37(6.24,-0.64) B38(4.97,-0.64) B39(3.7,-0.64) B40(2.43,-0.64) C1(51.96,0.63) C2(50.69,0.63) C3(49.42,0.63) C4(48.15,0.63) C5(46.88,0.63) C6(45.61,0.63) C7(44.34,0.63) C8(43.07,0.63) C9(41.8,0.63) C10(40.53,0.63) C11(39.26,0.63) C12(37.99,0.63) C13(36.72,0.63) C14(35.45,0.63) C15(34.18,0.63) C16(32.91,0.63) C17(31.64,0.63) C18(30.37,0.63) C19(29.1,0.63) C20(27.83,0.63) C21(26.56,0.63) C22(25.29,0.63) C23(24.02,0.63) C24(22.75,0.63) C25(21.48,0.63) C26(20.21,0.63) C27(18.94,0.63) C28(17.67,0.63) C29(16.4,0.63) C30(15.13,0.63) C31(13.86,0.63) C32(12.59,0.63) C33(11.32,0.63) C34(10.05,0.63) C35(8.78,0.63) C36(7.51,0.63) C37(6.24,0.63) C38(4.97,0.63) C39(3.7,0.63) C40(2.43,0.63) D1(51.96,1.9) D2(50.69,1.9) D3(49.42,1.9) D4(48.15,1.9) D5(46.88,1.9) D6(45.61,1.9) D7(44.34,1.9) D8(43.07,1.9) D9(41.8,1.9) D10(40.53,1.9) D11(39.26,1.9) D12(37.99,1.9) D13(36.72,1.9) D14(35.45,1.9) D15(34.18,1.9) D16(32.91,1.9) D17(31.64,1.9) D18(30.37,1.9) D19(29.1,1.9) D20(27.83,1.9) D21(26.56,1.9) D22(25.29,1.9) D23(24.02,1.9) D24(22.75,1.9) D25(21.48,1.9) D26(20.21,1.9) D27(18.94,1.9) D28(17.67,1.9) D29(16.4,1.9) D30(15.13,1.9) D31(13.86,1.9) D32(12.59,1.9) D33(11.32,1.9) D34(10.05,1.9) D35(8.78,1.9) D36(7.51,1.9) D37(6.24,1.9) D38(4.97,1.9) D39(3.7,1.9) D40(2.43,1.9)
10120667-101LF
  round 2.8 hole 2.2: 1(0,0) 2(12.03,0) 3(12.03,12) 4(12.03,24) 5(0,24)
  round 0.77 hole 0.37: A1_1(1.33,21) A1_2(1.33,9) A2_1(-0.07,20.25) A2_2(-0.07,8.25) A3_1(0.63,19.5) A3_2(0.63,7.5) A4_1(1.33,18.75) A4_2(1.33,6.75) A5_1(-0.07,18) A5_2(-0.07,6) A6_1(0.63,17.25) A6_2(0.63,5.25) A7_1(1.33,16.5) A7_2(1.33,4.5) A8_1(-0.07,15.75) A8_2(-0.07,3.75) A9_1(0.63,15) A9_2(0.63,3) B1_1(5.13,21) B1_2(5.13,9) B2_1(3.73,20.25) B2_2(3.73,8.25) B3_1(4.43,19.5) B3_2(4.43,7.5) B4_1(5.13,18.75) B4_2(5.13,6.75) B5_1(3.73,18) B5_2(3.73,6) B6_1(4.43,17.25) B6_2(4.43,5.25) B7_1(5.13,16.5) B7_2(5.13,4.5) B8_1(3.73,15.75) B8_2(3.73,3.75) B9_1(4.43,15) B9_2(4.43,3) C1_1(8.93,21) C1_2(8.93,9) C2_1(7.53,20.25) C2_2(7.53,8.25) C3_1(8.23,19.5) C3_2(8.23,7.5) C4_1(8.93,18.75) C4_2(8.93,6.75) C5_1(7.53,18) C5_2(7.53,6) C6_1(8.23,17.25) C6_2(8.23,5.25) C7_1(8.93,16.5) C7_2(8.93,4.5) C8_1(7.53,15.75) C8_2(7.53,3.75) C9_1(8.23,15) C9_2(8.23,3) D1_1(12.73,21) D1_2(12.73,9) D2_1(11.33,20.25) D2_2(11.33,8.25) D3_1(12.03,19.5) D3_2(12.03,7.5) D4_1(12.73,18.75) D4_2(12.73,6.75) D5_1(11.33,18) D5_2(11.33,6) D6_1(12.03,17.25) D6_2(12.03,5.25) D7_1(12.73,16.5) D7_2(12.73,4.5) D8_1(11.33,15.75) D8_2(11.33,3.75) D9_1(12.03,15) D9_2(12.03,3)
C210Q5_15033_Y
  oval 1.8x3.7 hole 1.2x3.1: 1(-4.36,-13.04) 2(65.32,-13.04)
  round 1.7 hole 1.1: A1(0,0) A2(2.54,0) A3(5.08,0) A4(7.62,0) A5(10.16,0) A6(12.7,0) A7(15.24,0) A8(17.78,0) A9(20.32,0) A10(22.86,0) A11(25.4,0) A12(27.94,0) A13(30.48,0) A14(33.02,0) A15(35.56,0) A16(38.1,0) A17(40.64,0) A18(43.18,0) A19(45.72,0) A20(48.26,0) A21(50.8,0) A22(53.34,0) A23(55.88,0) A24(58.42,0) A25(60.96,0) B1(0,-2.54) B2(2.54,-2.54) B3(5.08,-2.54) B4(7.62,-2.54) B5(10.16,-2.54) B6(12.7,-2.54) B7(15.24,-2.54) B8(17.78,-2.54) B9(20.32,-2.54) B10(22.86,-2.54) B11(25.4,-2.54) B12(27.94,-2.54) B13(30.48,-2.54) B14(33.02,-2.54) B15(35.56,-2.54) B16(38.1,-2.54) B17(40.64,-2.54) B18(43.18,-2.54) B19(45.72,-2.54) B20(48.26,-2.54) B21(50.8,-2.54) B22(53.34,-2.54) B23(55.88,-2.54) B24(58.42,-2.54) B25(60.96,-2.54)
C210R3-11631-Y
  rect 1.5x1.5 hole 0.9: 1(0,0)
  round 1.5 hole 0.9: 2(2.54,0) 3(5.08,0) 4(7.62,0) 5(10.16,0) 6(12.7,0) 7(15.24,0) 8(17.78,0) 9(17.78,2.54) 10(15.24,2.54) 11(12.7,2.54) 12(10.16,2.54) 13(7.62,2.54) 14(5.08,2.54) 15(2.54,2.54) 16(0,2.54)
C0402
  rect 0.559x0.559 smd: 1(-0.483,0) 2(0.483,0)
C0603
  rect 0.864x0.787 smd: 1(-0.737,0) 2(0.737,0)
C0805
  rect 1.118x1.27 smd: 1(-0.965,0) 2(0.965,0)
C1206
  rect 1.321x1.6 smd: 1(-1.575,0) 2(1.575,0)
C200126087D6001P
  rect 1.21x1.21 hole 0.81: 1(0,0)
  round 1.21 hole 0.81: 2(0,2) 3(2,0) 4(2,2) 5(4,0) 6(4,2) 7(6,0) 8(6,2) 9(8,0) 10(8,2) 11(10,0) 12(10,2) 13(12,0) 14(12,2) 15(14,0) 16(14,2) 17(16,0) 18(16,2) 19(18,0) 20(18,2) 21(20,0) 22(20,2) 23(22,0) 24(22,2) 25(24,0) 26(24,2)
CDNCC_0810
  rect 3.45x1.4 smd: 1(3.275,0) 2(-3.275,0)
CON_2
  rect 1.422x1.422 hole 1.016: 1(0,0)
  round 1.422 hole 1.016: 2(2.54,0)
JP_10
  rect 1.346x1.346 hole 0.94: 1(0,0)
  round 1.346 hole 0.94: 2(0,2.54) 3(2.54,0) 4(2.54,2.54) 5(5.08,0) 6(5.08,2.54) 7(7.62,0) 8(7.62,2.54) 9(10.16,0) 10(10.16,2.54)
L0805
  rect 1.118x1.27 smd: 1(-0.965,0) 2(0.965,0)
L_7M50X7M50X4M70
  rect 2.1x2.3 smd: 1(-3.15,0) 2(3.15,0)
LED_SMT0805
  rect 1.524x1.397 smd: 1(1.118,0) 2(-1.118,0)
MARK
  round 1.016 smd: 1(0,0)
MOLEX_44068_0048
  round 2.413 hole 1.803: 1(0,0) 2(-4.2,0) 3(-8.4,0) 4(-12.6,0) 5(-16.8,0) 6(0,4.2) 7(-4.2,4.2) 8(-8.4,4.2) 9(-12.6,4.2) 10(-16.8,4.2)
  round 3.81 hole 2.997: 11(6.2,-0.2) 12(-23,-0.2)
R0402
  rect 0.559x0.559 smd: 1(-0.483,0) 2(0.483,0)
R0603
  rect 0.864x0.787 smd: 1(-0.737,0) 2(0.737,0)
SCREW_HOLE_3_5MM
  round 7 hole 3.5: 1(0,0)
SCREW_N_M_3_5MM
  round 3.5 hole 3.5 unplated: (0,0)
  round 1.016 hole 0.508: 2(2.373,2.373) 3(0,3.355) 4(-2.373,2.373) 5(-3.355,0) 6(-2.373,-2.373) 7(0,-3.355) 8(2.373,-2.373) 9(3.355,0)
  custom 1.08x1.08 smd: 10(0,0) 11(0,0) 12(0,0) 13(0,0)
SO_8
  oval 0.711x1.778 smd: 1(-1.905,-2.87) 2(-0.635,-2.87) 3(0.635,-2.87) 4(1.905,-2.87) 5(1.905,2.87) 6(0.635,2.87) 7(-0.635,2.87) 8(-1.905,2.87)
SOT23_6_1M10
  rect 1.016x0.559 smd: 1(-1.35,0.95) 2(-1.35,0) 3(-1.35,-0.95) 4(1.35,-0.95) 5(1.35,0) 6(1.35,0.95)
SOT23_6_1M45
  rect 1.016x0.559 smd: 1(-1.35,0.95) 2(-1.35,0) 3(-1.35,-0.95) 4(1.35,-0.95) 5(1.35,0) 6(1.35,0.95)
SOT_23
  rect 1.321x1.016 smd: 1(1.143,-0.947) 2(1.143,0.947) 3(-1.143,0)
TEST_40
  round 1.016 smd: 1(0,0)
TQFP_144_1M60
  oval 1.5x0.25 smd: 1(-10.7,8.75) 2(-10.7,8.25) 3(-10.7,7.75) 4(-10.7,7.25) 5(-10.7,6.75) 6(-10.7,6.25) 7(-10.7,5.75) 8(-10.7,5.25) 9(-10.7,4.75) 10(-10.7,4.25) 11(-10.7,3.75) 12(-10.7,3.25) 13(-10.7,2.75) 14(-10.7,2.25) 15(-10.7,1.75) 16(-10.7,1.25) 17(-10.7,0.75) 18(-10.7,0.25) 19(-10.7,-0.25) 20(-10.7,-0.75) 21(-10.7,-1.25) 22(-10.7,-1.75) 23(-10.7,-2.25) 24(-10.7,-2.75) 25(-10.7,-3.25) 26(-10.7,-3.75) 27(-10.7,-4.25) 28(-10.7,-4.75) 29(-10.7,-5.25) 30(-10.7,-5.75) 31(-10.7,-6.25) 32(-10.7,-6.75) 33(-10.7,-7.25) 34(-10.7,-7.75) 35(-10.7,-8.25) 36(-10.7,-8.75) 73(10.7,-8.75) 74(10.7,-8.25) 75(10.7,-7.75) 76(10.7,-7.25) 77(10.7,-6.75) 78(10.7,-6.25) 79(10.7,-5.75) 80(10.7,-5.25) 81(10.7,-4.75) 82(10.7,-4.25) 83(10.7,-3.75) 84(10.7,-3.25) 85(10.7,-2.75) 86(10.7,-2.25) 87(10.7,-1.75) 88(10.7,-1.25) 89(10.7,-0.75) 90(10.7,-0.25) 91(10.7,0.25) 92(10.7,0.75) 93(10.7,1.25) 94(10.7,1.75) 95(10.7,2.25) 96(10.7,2.75) 97(10.7,3.25) 98(10.7,3.75) 99(10.7,4.25) 100(10.7,4.75) 101(10.7,5.25) 102(10.7,5.75) 103(10.7,6.25) 104(10.7,6.75) 105(10.7,7.25) 106(10.7,7.75) 107(10.7,8.25) 108(10.7,8.75)
  oval 0.25x1.5 smd: 37(-8.75,-10.7) 38(-8.25,-10.7) 39(-7.75,-10.7) 40(-7.25,-10.7) 41(-6.75,-10.7) 42(-6.25,-10.7) 43(-5.75,-10.7) 44(-5.25,-10.7) 45(-4.75,-10.7) 46(-4.25,-10.7) 47(-3.75,-10.7) 48(-3.25,-10.7) 49(-2.75,-10.7) 50(-2.25,-10.7) 51(-1.75,-10.7) 52(-1.25,-10.7) 53(-0.75,-10.7) 54(-0.25,-10.7) 55(0.25,-10.7) 56(0.75,-10.7) 57(1.25,-10.7) 58(1.75,-10.7) 59(2.25,-10.7) 60(2.75,-10.7) 61(3.25,-10.7) 62(3.75,-10.7) 63(4.25,-10.7) 64(4.75,-10.7) 65(5.25,-10.7) 66(5.75,-10.7) 67(6.25,-10.7) 68(6.75,-10.7) 69(7.25,-10.7) 70(7.75,-10.7) 71(8.25,-10.7) 72(8.75,-10.7) 109(8.75,10.7) 110(8.25,10.7) 111(7.75,10.7) 112(7.25,10.7) 113(6.75,10.7) 114(6.25,10.7) 115(5.75,10.7) 116(5.25,10.7) 117(4.75,10.7) 118(4.25,10.7) 119(3.75,10.7) 120(3.25,10.7) 121(2.75,10.7) 122(2.25,10.7) 123(1.75,10.7) 124(1.25,10.7) 125(0.75,10.7) 126(0.25,10.7) 127(-0.25,10.7) 128(-0.75,10.7) 129(-1.25,10.7) 130(-1.75,10.7) 131(-2.25,10.7) 132(-2.75,10.7) 133(-3.25,10.7) 134(-3.75,10.7) 135(-4.25,10.7) 136(-4.75,10.7) 137(-5.25,10.7) 138(-5.75,10.7) 139(-6.25,10.7) 140(-6.75,10.7) 141(-7.25,10.7) 142(-7.75,10.7) 143(-8.25,10.7) 144(-8.75,10.7)
TSSOP_16_1M10
  oval 0.35x1.5 smd: 1(-2.275,-2.95) 2(-1.625,-2.95) 3(-0.975,-2.95) 4(-0.325,-2.95) 5(0.325,-2.95) 6(0.975,-2.95) 7(1.625,-2.95) 8(2.275,-2.95) 9(2.275,2.95) 10(1.625,2.95) 11(0.975,2.95) 12(0.325,2.95) 13(-0.325,2.95) 14(-0.975,2.95) 15(-1.625,2.95) 16(-2.275,2.95)
TSSOP_20
  oval 0.3x1.5 smd: 1(-2.925,-2.86) 2(-2.275,-2.86) 3(-1.625,-2.86) 4(-0.975,-2.86) 5(-0.325,-2.86) 6(0.325,-2.86) 7(0.975,-2.86) 8(1.625,-2.86) 9(2.275,-2.86) 10(2.925,-2.86) 11(2.925,2.86) 12(2.275,2.86) 13(1.625,2.86) 14(0.975,2.86) 15(0.325,2.86) 16(-0.325,2.86) 17(-0.975,2.86) 18(-1.625,2.86) 19(-2.275,2.86) 20(-2.925,2.86)
TSSOP_24
  oval 0.305x1.524 smd: 1(-3.575,-2.925) 2(-2.925,-2.925) 3(-2.275,-2.925) 4(-1.625,-2.925) 5(-0.975,-2.925) 6(-0.325,-2.925) 7(0.325,-2.925) 8(0.975,-2.925) 9(1.625,-2.925) 10(2.275,-2.925) 11(2.925,-2.925) 12(3.575,-2.925) 13(3.575,2.925) 14(2.925,2.925) 15(2.275,2.925) 16(1.625,2.925) 17(0.975,2.925) 18(0.325,2.925) 19(-0.325,2.925) 20(-0.975,2.925) 21(-1.625,2.925) 22(-2.275,2.925) 23(-2.925,2.925) 24(-3.575,2.925)

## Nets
12V_LOAD_SHARE: J8.B23(12 V LOAD SHARE) J9.B23(12 V LOAD SHARE)
GND: C1.1 C2.1 C3.1 C4.1 C5.1 C6.1 C7.1 C8.1 C9.1 C10.1 C16.2 C17.2 C18.2 C19.1 C20.1 C21.1 C22.1 C23.1 C28.1 C29.2 C30.2 C48.1 C49.1 C50.1 C51.1 C52.1 C53.2 C54.2 C55.1 C56.2 C57.2 C61.2 C62.2 C63.1 C64.2 C65.2 C66.2 C67.1 C68.1 C69.1 C70.1 C71.1 C72.1 C73.1 C74.1 C75.1 C77.1 C78.1 C79.1 C80.1 C81.1 C82.1 C83.1 C84.1 C85.1 C86.1 C87.1 C89.1 C90.1 C94.2 C95.2 C96.2 C97.2 C98.2 C99.2 C100.1 C101.1 C104.2 C105.2 C106.2 C107.2 C108.2 C109.2 C110.2 C111.2 C112.2 C113.2 C114.1 C116.2 C117.1 C120.2 C121.2 C129.2 C130.2 C131.1 C132.1 C133.1 C134.2 C135.2 C136.2 C137.2 C138.2 C139.2 C140.2 C141.2 C142.2 C143.2 C144.2 C145.2 C146.2 C147.2 C148.2 C149.2 C150.1 C151.1 C152.1 C153.1 C154.1 C155.1 C156.2 C157.1 C158.1 CD1.2 CD2.2 CD4.2 CD5.2 CD7.2 CD8.2 D1.2(CATHODE) D3.2(CATHODE) J1.1 J1.2 J1.3 J1.4 J1.5 J2.9 J2.10 J2.11 J3.1 J3.2 J3.3 J3.4 J3.5 J4.9 J4.10 J4.11 J5.9 J5.10 J5.11 J7.2 J7.10 J8.A1(GND_1) J8.A2(GND_2) J8.A3(GND_3) J8.A4(GND_4) J8.A5(GND_5) J8.A6(GND_6) J8.A7(GND_7) J8.A8(GND_8) J8.A9(GND_9) J8.A23(VSENSE-) J8.B1(GND_10) J8.B2(GND_11) J8.B3(GND_12) J8.B4(GND_13) J8.B5(GND_14) J8.B6(GND_15) J8.B7(GND_16) J8.B8(GND_17) J8.B9(GND_18) J9.A1(GND_1) J9.A2(GND_2) J9.A3(GND_3) J9.A4(GND_4) J9.A5(GND_5) J9.A6(GND_6) J9.A7(GND_7) J9.A8(GND_8) J9.A9(GND_9) J9.A23(VSENSE-) J9.B1(GND_10) J9.B2(GND_11) J9.B3(GND_12) J9.B4(GND_13) J9.B5(GND_14) J9.B6(GND_15) J9.B7(GND_16) J9.B8(GND_17) J9.B9(GND_18) J10.1 J10.4 J10.7 J10.10 J10.13 J10.16 J10.18 J10.20 J10.23 J10.25 Q1.2(E) Q3.2(E) Q4.2(E) Q7.2(E) Q8.2(E) Q9.2(E) Q10.2(E) Q11.2(E) Q12.2(E) Q13.2(E) Q14.2(E) Q15.2(E) Q16.2(E) R45.2 R69.2 R87.2 R109.2 R127.2 R130.2 R171.2 R172.2 R173.2 R174.1 R180.2 R181.2 R182.2 R183.1 R198.2 R200.1 R201.1 R205.2 R206.2 R207.2 R209.1 R222.2 R223.2 R226.2 R244.1 R245.1 R246.1 R253.1 R259.1 R264.2 R266.1 R276.2 R279.1 R282.1 R285.1 R289.2 R293.2 R295.2 R298.2 R332.1 R350.1 R355.1 U1.8(GND_1) U1.18(GND_2) U1.29(GND_3) U1.46(GND_4) U1.53(GND_5) U1.64(GND_6) U1.80(GND_7) U1.90(GND_8) U1.101(GND_9) U1.116(GND_10) U1.124(GND_11) U1.134(GND_12) U2.10(GND) U3.1(GND) U4.1(GND) U5.2(GND) U7.4(GND) U8.12(VSS) U9.A4 U9.A7 U9.A10 U9.A13 U9.A15 U9.A16 U9.A18 U9.A19 U9.A21 U9.A22 U9.A24 U9.A25 U9.A27 U9.A28 U9.A30 U9.A33 U9.A36 U9.A39 U9.B2 U9.B3 U9.B5 U9.B6 U9.B8 U9.B9 U9.B11 U9.B12 U9.B14 U9.B17 U9.B20 U9.B23 U9.B26 U9.B29 U9.B31 U9.B32 U9.B34 U9.B35 U9.B39 U9.C1 U9.C4 U9.C7 U9.C10 U9.C13 U9.C15 U9.C16 U9.C18 U9.C19 U9.C21 U9.C22 U9.C24 U9.C25 U9.C27 U9.C28 U9.C30 U9.C33 U9.C36 U9.C39 U9.D2 U9.D3 U9.D5 U9.D6 U9.D8 U9.D9 U9.D11 U9.D12 U9.D14 U9.D17 U9.D20 U9.D23 U9.D26 U9.D29 U9.D31 U9.D32 U9.D34 U9.D35 U9.D37 U9.D39 U10.8(VSS) X19.1 X21.1 X23.1 X25.1 X26.2 X26.3 X26.4 X26.5 X26.6 X26.7 X26.8 X26.9 X26.10 X26.11 X26.12 X26.13 X27.2 X27.3 X27.4 X27.5 X27.6 X27.7 X27.8 X27.9 X27.10 X27.11 X27.12 X27.13 X28.2 X28.3 X28.4 X28.5 X28.6 X28.7 X28.8 X28.9 X28.10 X28.11 X28.12 X28.13 X29.2 X29.3 X29.4 X29.5 X29.6 X29.7 X29.8 X29.9 X29.10 X29.11 X29.12 X29.13 X30.2 X30.3 X30.4 X30.5 X30.6 X30.7 X30.8 X30.9 X30.10 X30.11 X30.12 X30.13 X31.2 X31.3 X31.4 X31.5 X31.6 X31.7 X31.8 X31.9 X31.10 X31.11 X31.12 X31.13 X32.2 X32.3 X32.4 X32.5 X32.6 X32.7 X32.8 X32.9 X32.10 X32.11 X32.12 X32.13 X33.2 X33.3 X33.4 X33.5 X33.6 X33.7 X33.8 X33.9 X33.10 X33.11 X33.12 X33.13 X34.2 X34.3 X34.4 X34.5 X34.6 X34.7 X34.8 X34.9 X34.10 X34.11 X34.12 X34.13 X35.2 X35.3 X35.4 X35.5 X35.6 X35.7 X35.8 X35.9 X35.10 X35.11 X35.12 X35.13 X36.2 X36.3 X36.4 X36.5 X36.6 X36.7 X36.8 X36.9 X36.10 X36.11 X36.12 X36.13 X37.2 X37.3 X37.4 X37.5 X37.6 X37.7 X37.8 X37.9 X37.10 X37.11 X37.12 X37.13 X38.2 X38.3 X38.4 X38.5 X38.6 X38.7 X38.8 X38.9 X38.10 X38.11 X38.12 X38.13 X39.2 X39.3 X39.4 X39.5 X39.6 X39.7 X39.8 X39.9 X39.10 X39.11 X39.12 X39.13 X40.2 X40.3 X40.4 X40.5 X40.6 X40.7 X40.8 X40.9 X40.10 X40.11 X40.12 X40.13 X41.2 X41.3 X41.4 X41.5 X41.6 X41.7 X41.8 X41.9 X41.10 X41.11 X41.12 X41.13 X42.2 X42.3 X42.4 X42.5 X42.6 X42.7 X42.8 X42.9 X42.10 X42.11 X42.12 X42.13 X43.2 X43.3 X43.4 X43.5 X43.6 X43.7 X43.8 X43.9 X43.10 X43.11 X43.12 X43.13 X44.2 X44.3 X44.4 X44.5 X44.6 X44.7 X44.8 X44.9 X44.10 X44.11 X44.12 X44.13 X45.2 X45.3 X45.4 X45.5 X45.6 X45.7 X45.8 X45.9 X45.10 X45.11 X45.12 X45.13 X46.2 X46.3 X46.4 X46.5 X46.6 X46.7 X46.8 X46.9 X46.10 X46.11 X46.12 X46.13 X47.1 X48.2 X48.3 X48.4 X48.5 X48.6 X48.7 X48.8 X48.9 X48.10 X48.11 X48.12 X48.13 X49.2 X49.3 X49.4 X49.5 X49.6 X49.7 X49.8 X49.9 X49.10 X49.11 X49.12 X49.13 X50.2 X50.3 X50.4 X50.5 X50.6 X50.7 X50.8 X50.9 X50.10 X50.11 X50.12 X50.13 X54.2 X54.3 X54.4 X54.5 X54.6 X54.7 X54.8 X54.9 X54.10 X54.11 X54.12 X54.13 X55.1 X56.1 X58.2 X58.3 X58.4 X58.5 X58.6 X58.7 X58.8 X58.9 X58.10 X58.11 X58.12 X58.13 YJ1.1(GND_25) YJ1.2(GND_26) YJ1.3(GND_27) YJ1.4(GND_28) YJ1.5(GND_29) YJ1.A3_1(GND_1) YJ1.A3_2(GND_13) YJ1.A6_1(GND_2) YJ1.A6_2(GND_14) YJ1.A9_1(GND_3) YJ1.A9_2(GND_15) YJ1.B3_1(GND_4) YJ1.B3_2(GND_16) YJ1.B6_1(GND_5) YJ1.B6_2(GND_17) YJ1.B9_1(GND_6) YJ1.B9_2(GND_18) YJ1.C3_1(GND_7) YJ1.C3_2(GND_19) YJ1.C6_1(GND_8) YJ1.C6_2(GND_20) YJ1.C9_1(GND_9) YJ1.C9_2(GND_21) YJ1.D3_1(GND_10) YJ1.D3_2(GND_22) YJ1.D6_1(GND_11) YJ1.D6_2(GND_23) YJ1.D9_1(GND_12) YJ1.D9_2(GND_24)
VDD5V: C103.1 C104.1 C111.1 C112.1 C113.1 C114.2 L2.1 L3.2 R204.1 R265.1 X24.1
VDD5V_EN: Q7.3(C) R193.2 R198.1 U4.5(EN)
VDD12V: C28.2 C29.1 C30.1 C52.2 C53.1 C54.1 C55.2 C56.1 C57.1 C67.2 C68.2 C69.2 C70.2 C71.2 C72.2 C79.2 C80.2 C81.2 C82.2 C83.2 C84.2 C94.1 C95.1 C96.1 C108.1 C109.1 C110.1 C131.2 C132.2 C133.2 C151.2 C152.2 C153.2 CD1.1 CD2.1 CD4.1 CD5.1 CD7.1 CD8.1 J1.6 J1.7 J1.8 J1.9 J1.10 J2.7 J2.8 J3.6 J3.7 J3.8 J3.9 J3.10 J4.7 J4.8 J5.7 J5.8 J8.A10(+12V_1) J8.A11(+12V_2) J8.A12(+12V_3) J8.A13(+12V_4) J8.A14(+12V_5) J8.A15(+12V_6) J8.A16(+12V_7) J8.A17(+12V_8) J8.A18(+12V_9) J8.A24(VSENSE+) J8.B10(+12V_10) J8.B11(+12V_11) J8.B12(+12V_12) J8.B13(+12V_13) J8.B14(+12V_14) J8.B15(+12V_15) J8.B16(+12V_16) J8.B17(+12V_17) J8.B18(+12V_18) J9.A10(+12V_1) J9.A11(+12V_2) J9.A12(+12V_3) J9.A13(+12V_4) J9.A14(+12V_5) J9.A15(+12V_6) J9.A16(+12V_7) J9.A17(+12V_8) J9.A18(+12V_9) J9.A24(VSENSE+) J9.B10(+12V_10) J9.B11(+12V_11) J9.B12(+12V_12) J9.B13(+12V_13) J9.B14(+12V_14) J9.B15(+12V_15) J9.B16(+12V_16) J9.B17(+12V_17) J9.B18(+12V_18) R193.1 R196.1 R199.1 R261.1 R262.1 U3.3(VIN) U4.3(VIN) U9.A40 U9.B40 U9.C40 U9.D40 X18.1 X20.1
VDD12VSB: C74.2 C77.2 C87.2 C89.2 J8.B21(12 VSB) J9.B21(12 VSB)
9548_RST#: R128.2 R240.2 U8.3(R\E\S\E\T\)
ALL_RESET#: R109.1 R110.1 U1.107(PR2A) U9.C26
BMC_9641_INT#: R303.1 U9.A2
BMC_I2C_RST#: R117.2 U9.D36
BMC_I2C_SCL: R115.1 R309.2 U1.126(PT12C/SCL/PCLKT0_0) U9.B33 U10.5(SCL_MST1)
BMC_I2C_SDA: R16.2 R123.1 R301.1 R310.2 U9.D33
BMC_RESERVE1: R249.2 U9.C38
CPLD3.3V: C1.2 C2.2 C3.2 C4.2 C5.2 C6.2 C7.2 C8.2 C9.2 C10.2 C16.1 C17.1 C18.1 C19.2 C20.2 C21.2 C22.2 C23.2 C48.2 C49.2 C50.2 C51.2 C63.2 C64.1 C65.1 C66.1 C92.1 C97.1 C98.1 C99.1 C100.2 C116.1 C117.2 C154.2 C155.2 C156.1 C157.2 D2.3(A1/A2) J7.4 L1.1 R17.2 R46.2 R47.2 R89.2 R110.2 R112.2 R113.2 R115.2 R118.2 R122.2 R123.2 R131.1 R133.1 R143.2 R150.1 R154.2 R158.2 R160.2 R161.2 R163.2 R164.2 R166.2 R167.2 R194.1 R195.1 R220.2 R224.2 R225.2 R227.1 R228.1 R229.1 R230.1 R231.1 R232.1 R240.1 R241.1 R242.1 R243.1 R252.1 R254.1 R255.1 R256.2 R257.2 R258.1 R260.1 R268.2 R270.2 R271.2 R273.2 R274.2 R275.2 R277.1 R278.2 R280.1 R281.2 R283.1 R284.2 R292.2 R294.2 R296.2 R297.1 R299.2 R304.1 R305.2 R306.1 R318.2 R319.2 R328.1 R329.2 R333.2 R339.2 R345.2 R346.1 R347.2 R351.1 R352.2 R356.2 U1.7(VCCIO3_1) U1.16(VCCIO3_2) U1.30(VCCIO3_3) U1.36(VCC_1) U1.37(VCCIO2_1) U1.51(VCCIO2_2) U1.66(VCCIO2_3) U1.72(VCC_2) U1.79(VCCIO1_1) U1.88(VCCIO1_2) U1.102(VCCIO1_3) U1.108(VCC_3) U1.118(VCCIO0_1) U1.123(VCCIO0_2) U1.135(VCCIO0_3) U1.144(VCC_4) U2.20(POWER) U7.8(VCC) U8.24(VDD) U10.16(VDD) X22.1
CPLD3.3V_EN: Q9.3(C) R261.2 R264.1 U3.5(EN)
CPLD_DOWNLOAD_OK: R119.1 U1.106(PR2B)
CPLD_TCK: R45.1 R48.1 R146.2 U1.131(PT11C/TCK)
CPLD_TDI: R47.1 R51.1 R151.2 U1.136(PT10D/TDI)
CPLD_TDO: J7.3 R4.2 U2.15(2A1)
CPLD_TMS: R46.1 R49.1 R148.2 U1.130(PT11D/TMS)
CPU_9641_INT#: R290.1 U9.A3
CPU_I2C_RST#: C149.1 U9.C17 YJ1.A1_1(SIDEBAND7_1)
CPU_I2C_SCL: R154.1 R307.2 U1.11(PL4A) U9.D13 U10.3(SCL_MST0)
CPU_I2C_SDA: R157.2 R158.1 R291.1 R308.2 U9.C14
CPU_KR_RDN0: U9.C9 YJ1.B7_2(RX2+_2)
CPU_KR_RDN1: U9.C12 YJ1.B7_1(RX2+_1)
CPU_KR_RDP0: U9.C8 YJ1.B8_2(RX2-_2)
CPU_KR_RDP1: U9.C11 YJ1.B8_1(RX2-_1)
CPU_KR_TDN0: U9.B22 YJ1.D8_2(TX2-_2)
CPU_KR_TDN1: U9.D22 YJ1.D7_1(TX2+_1)
CPU_KR_TDP0: U9.B21 YJ1.D7_2(TX2+_2)
CPU_KR_TDP1: U9.D21 YJ1.D8_1(TX2-_1)
CPU_ONLINE_TCK: R253.2 U2.2(1A0) U2.4(1A1) U9.B4
CPU_ONLINE_TDI: R155.2 U9.D4
CPU_ONLINE_TDO: R254.2 U2.17(2A0) U9.B10
CPU_ONLINE_TMS: R252.2 U2.6(1A2) U2.8(1A3) U9.B13
CPU_PCIE_RXN0: U9.C3 YJ1.B5_1(RX0-_1)
CPU_PCIE_RXN1: U9.A6 YJ1.A5_1(RX1-_1)
CPU_PCIE_RXN2: U9.C6 YJ1.B5_2(RX0-_2)
CPU_PCIE_RXN3: U9.A9 YJ1.A5_2(RX1-_2)
CPU_PCIE_RXP0: U9.C2 YJ1.B4_1(RX0+_1)
CPU_PCIE_RXP1: U9.A5 YJ1.A4_1(RX1+_1)
CPU_PCIE_RXP2: U9.C5 YJ1.B4_2(RX0+_2)
CPU_PCIE_RXP3: U9.A8 YJ1.A4_2(RX1+_2)
CPU_PCIE_TXN0: U9.B16 YJ1.D4_1(TX0+_1)
CPU_PCIE_TXN1: U9.D16 YJ1.C5_1(TX1-_1)
CPU_PCIE_TXN2: U9.B19 YJ1.D5_2(TX0-_2)
CPU_PCIE_TXN3: U9.D19 YJ1.C5_2(TX1-_2)
CPU_PCIE_TXP0: U9.B15 YJ1.D5_1(TX0-_1)
CPU_PCIE_TXP1: U9.D15 YJ1.C4_1(TX1+_1)
CPU_PCIE_TXP2: U9.B18 YJ1.D4_2(TX0+_2)
CPU_PCIE_TXP3: U9.D18 YJ1.C4_2(TX1+_2)
CPU_RESERVE1: R250.2 U9.B37
CPU_RESERVE2: R251.2 U9.B38
CR: R176.2 R180.1 R185.2
FAN0_E2_WP: J2.6 R54.2
FAN0_EN: J2.2 R327.2 R333.1
FAN0_LED1: J2.5 U1.27(PL9A/PCLKT3_0)
FAN0_LED2: J2.12 U1.26(PL8D)
FAN0_POWER_OK#: R97.1 R161.1 U1.34(PL10C)
FAN0_PRESENT_IN#: R96.1 R160.1 U1.35(PL10D)
FAN0_PWM: J2.15 U1.28(PL9B/PCLKC3_0)
FAN0_SCL: J2.4 R228.2 U8.5(SC0)
FAN0_SDA: J2.13 R227.2 U8.4(SD0)
FAN0_TACH: Q11.3(C) R277.2 R311.2 U1.33(PL10B)
FAN0_TACH_RESERVE: J2.16 R329.1 R330.1 R331.1
FAN0_TACH_RESERVE_CPLD: Q14.3(C) R328.2 R330.2 U1.76(PR10A)
FAN1_E2_WP: J4.6 R6.2
FAN1_EN: J4.2 R326.2 R339.1
FAN1_LED1: J4.5 U1.14(PL4D)
FAN1_LED2: J4.12 U1.20(PL5B/PCLKC3_1)
FAN1_POWER_OK#: R100.1 R164.1 U1.23(PL8A)
FAN1_PRESENT_IN#: R99.1 R163.1 U1.24(PL8B)
FAN1_PWM: J4.15 U1.21(PL5C)
FAN1_SCL: J4.4 R230.2 U8.7(SC1)
FAN1_SDA: J4.13 R229.2 U8.6(SD1)
FAN1_TACH: Q12.3(C) R280.2 R312.2 U1.22(PL5D)
FAN1_TACH_RESERVE: J4.16 R347.1 R348.1 R349.1
FAN1_TACH_RESERVE_CPLD: Q15.3(C) R346.2 R348.2 U1.75(PR10B)
FAN2_E2_WP: J5.6 R31.2
FAN2_EN: J5.2 R325.2 R345.1
FAN2_LED1: J5.5 U1.4(PL2D/L_GPLLC_IN)
FAN2_LED2: J5.12 U1.2(PL2B/L_GPLLC_FB)
FAN2_POWER_OK#: R103.1 R167.1 U1.10(PL3D)
FAN2_PRESENT_IN#: R102.1 R166.1 U1.6(PL3B/PCLKC3_2)
FAN2_PWM: J5.15 U1.1(PL2A/L_GPLLT_FB)
FAN2_SCL: J5.4 R232.2 U8.9(SC2)
FAN2_SDA: J5.13 R231.2 U8.8(SD2)
FAN2_TACH: Q13.3(C) R283.2 R313.2 U1.9(PL3C)
FAN2_TACH_RESERVE: J5.16 R352.1 R353.1 R354.1
FAN2_TACH_RESERVE_CPLD: Q16.3(C) R351.2 R353.2 U1.74(PR10C)
GPIO_I2C_SCL: R268.1 U1.47(PB9C) U9.B27 YJ1.A8_1(RX3-_1)
GPIO_I2C_SDA: R269.2 R270.1 U9.B28 YJ1.A7_1(RX3+_1)
LM75_INT#: R118.1 R221.1 U1.138(PT10B*)
LPC_LAD0: R126.2 U9.A23
LPC_LAD0_CPLD: C142.1 R314.2 YJ1.A2_1(SIDEBAND0_1)
LPC_LAD1: R129.2 U9.A26
LPC_LAD1_CPLD: C143.1 R315.2 YJ1.B2_1(SIDEBAND1_1)
LPC_LAD2: R132.2 U9.A29
LPC_LAD2_CPLD: C144.1 R316.2 YJ1.C2_1(SIDEBAND2_1)
LPC_LAD3: R134.2 U9.B30
LPC_LAD3_CPLD: C145.1 R317.2 YJ1.B1_1(SIDEBAND3_1)
LPC_LCLK: R136.2 U9.A14
LPC_LCLK_CPLD: C146.1 R320.2 YJ1.C1_1(SIDEBAND4_1)
LPC_LFRAME#: R137.2 U9.A20
LPC_LFRAME#_CPLD: C147.1 R322.2 YJ1.D1_1(SIDEBAND5_1)
LPC_SERIRQ: R139.2 U9.A17
LPC_SERIRQ_CPLD: C148.1 R324.2 YJ1.D2_1(SIDEBAND6_1)
MDI_0N: J10.2 U9.A32
MDI_0P: J10.3 U9.A31
MDI_1N: J10.5 U9.C32
MDI_1P: J10.6 U9.C31
MDI_2N: J10.8 U9.A35
MDI_2P: J10.9 U9.A34
MDI_3N: J10.11 U9.C35
MDI_3P: J10.12 U9.C34
MGMT LED_ACT: U1.141(PT9C) U9.B36
MGMT LED_LINK_100: U1.143(PT9A*) U9.A37
MGMT LED_LINK_1000: U1.142(PT9B*) U9.A38
MGMT_LED_GREEN: C129.1 J10.24 U1.97(PR4B)
MGMT_LED_LINKACT: C130.1 J10.26 U1.98(PR4A)
MOD_PRE0: U9.A1 U9.D38
ONLINE_CPLD_UPDATE1: R153.1 U2.11(2A3) U9.B7
ONLINE_CPLD_UPDATE2: C138.1 R156.2 YJ1.C1_2(SIDEBAND4_2)
ONLINE_TCK: C136.1 R147.2 YJ1.C2_2(SIDEBAND2_2)
ONLINE_TDI: C134.1 R255.2 U2.13(2A2) YJ1.A2_2(SIDEBAND0_2)
ONLINE_TDO: C135.1 R152.2 YJ1.B2_2(SIDEBAND1_2)
ONLINE_TMS: C137.1 R149.2 YJ1.B1_2(SIDEBAND3_2)
PCA9641_RST#: R58.2 R297.2 U10.4(R\E\S\E\T\)
PCA9641_SCL: R271.1 R300.2 R306.2 U1.68(PB20A) U7.2(SCL) U8.22(SCL) YJ1.A8_2(RX3-_2)
PCA9641_SDA: R219.1 R239.1 R272.2 R273.1 R302.2 R304.2 YJ1.A7_2(RX3+_2)
